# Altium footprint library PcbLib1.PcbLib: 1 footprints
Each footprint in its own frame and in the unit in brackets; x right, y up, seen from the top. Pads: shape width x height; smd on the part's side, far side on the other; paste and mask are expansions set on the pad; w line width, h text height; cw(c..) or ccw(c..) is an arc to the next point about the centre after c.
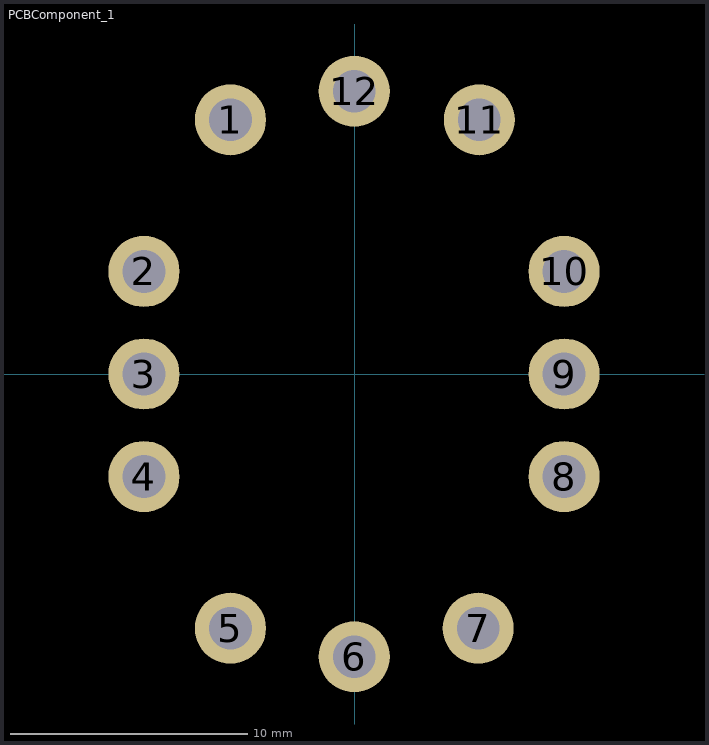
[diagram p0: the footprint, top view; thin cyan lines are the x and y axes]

## PCBComponent_1 [mm]
pads (12):
  round 3 hole 1.8: 1(-5.25,10.725) 2(-8.9,4.325) 3(-8.9,0) 4(-8.9,-4.325) 5(-5.25,-10.725) 6(-0.025,-11.925) 7(5.2,-10.725) 8(8.825,-4.325) 9(8.825,0) 10(8.825,4.325) 11(5.25,10.725) 12(-0.025,11.925)
Outline:
  circle w0.013: c-8.9,4.322 r0.889
  circle w0.013: c-8.9,0.004 r0.889
  circle w0.013: c-8.9,-4.314 r0.889
  circle w0.013: c8.829,0.004 r0.889
  circle w0.013: c8.829,4.322 r0.889
  circle w0.013: c8.829,-4.314 r0.889
  circle w0.013: c-0.035,11.93 r0.889
  circle w0.013: c5.192,10.723 r0.889
  circle w0.013: c-5.263,-10.714 r0.889
  circle w0.013: c-0.035,-11.921 r0.889
  circle w0.013: c-5.263,10.723 r0.889
  circle w0.013: c5.192,-10.714 r0.889
  text "2" at -11.675,5.35 h1.52
  text "1" at -7.925,12.2 h1.52
3D body: height 12.71, standoff 0, extent -9.754,-12.814 9.754,12.814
